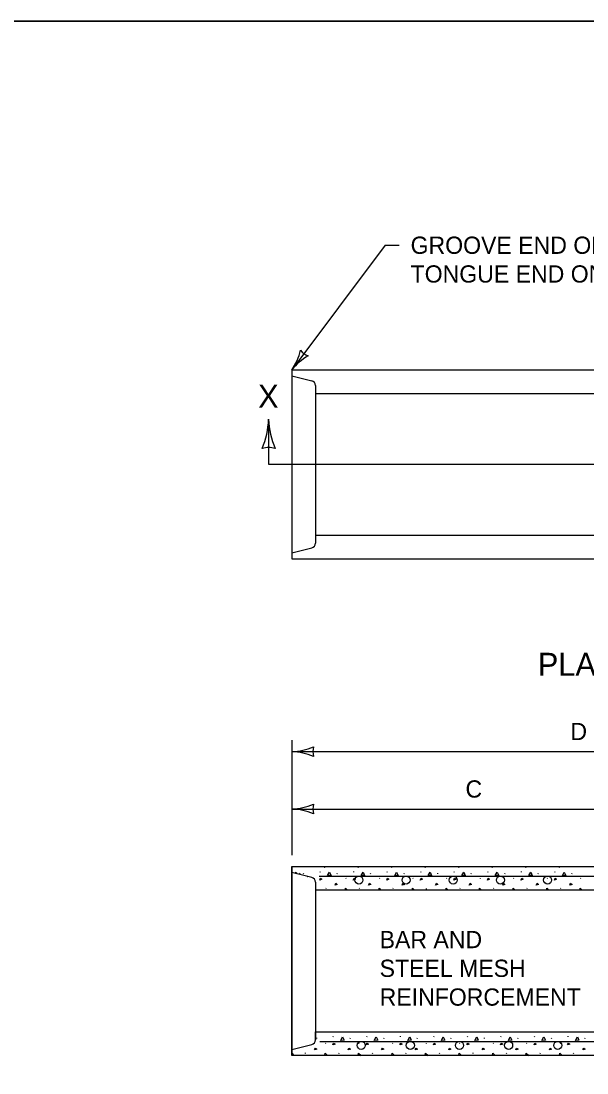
# Model space of a CAD drawing. Extents: x 49991.4 to 50021, y 49987.6 to 50011.4.
# Drawn here: x 50008.666 to 50010.636, y 49995.339 to 49998.999 of the extents above; entities that cross this region are included whole.
import ezdxf

# ---------------------------------------------------------------- set-up
doc = ezdxf.new("R2010")
doc.units = 0
for name, color, linetype in [('Level 1', 7, 'Continuous'), ('Level 2', 7, 'Continuous'), ('Level 3', 7, 'Continuous'), ('Level 4', 7, 'Continuous'), ('Level 6', 7, 'Continuous')]:
    doc.layers.add(name, color=color, linetype=linetype)

msp = doc.modelspace()

# ---------------------------------------------------------------- linework, layer by layer
at = {"layer": 'Level 1'}
for p, q in [((50009.6084, 49997.7858), (50009.6084, 49997.1282)), ((50009.6084, 49997.7858), (50010.8686, 49997.7858)), ((50009.6084, 49997.1282), (50010.8686, 49997.1282)), ((50009.6084, 49996.0573), (50010.8686, 49996.0573)), ((50009.6084, 49996.0573), (50009.6084, 49995.3998)), ((50009.6084, 49995.3998), (50009.6084, 49996.0573)), ((50009.6084, 49995.4204), (50009.6084, 49996.0573)), ((50009.6782, 49996.019), (50009.6084, 49996.0367)), ((50009.6362, 49996.0335), (50009.6372, 49996.0357)), ((50009.6693, 49996.0561), (50009.6698, 49996.0573)), ((50009.7073, 49996.038), (50009.7083, 49996.0402)), ((50009.7217, 49996.0561), (50009.7227, 49996.0546)), ((50009.7227, 49996.0555), (50009.7236, 49996.0541)), ((50009.786, 49996.0561), (50009.7865, 49996.0573)), ((50009.824, 49996.038), (50009.825, 49996.0402)), ((50009.8384, 49996.0561), (50009.8394, 49996.0546)), ((50009.8394, 49996.0555), (50009.8403, 49996.0541)), ((50009.9027, 49996.0561), (50009.9032, 49996.0573)), ((50009.9407, 49996.038), (50009.9417, 49996.0402)), ((50009.9551, 49996.0561), (50009.956, 49996.0546)), ((50009.956, 49996.0555), (50009.957, 49996.0541)), ((50010.0194, 49996.0561), (50010.0199, 49996.0573)), ((50010.0574, 49996.038), (50010.0584, 49996.0402)), ((50010.0718, 49996.0561), (50010.0727, 49996.0546)), ((50010.0727, 49996.0555), (50010.0737, 49996.0541)), ((50010.1361, 49996.0561), (50010.1366, 49996.0573)), ((50010.1741, 49996.038), (50010.175, 49996.0402)), ((50010.1884, 49996.0561), (50010.1894, 49996.0546)), ((50010.1894, 49996.0555), (50010.1904, 49996.0541)), ((50010.2528, 49996.0561), (50010.2533, 49996.0573)), ((50010.2908, 49996.038), (50010.2917, 49996.0402)), ((50010.3051, 49996.0561), (50010.3061, 49996.0546)), ((50010.3061, 49996.0555), (50010.3071, 49996.0541)), ((50010.3694, 49996.0561), (50010.3699, 49996.0573)), ((50010.4075, 49996.038), (50010.4084, 49996.0402)), ((50010.4218, 49996.0561), (50010.4228, 49996.0546)), ((50010.4228, 49996.0555), (50010.4238, 49996.0541)), ((50010.4861, 49996.0561), (50010.4866, 49996.0573)), ((50010.5241, 49996.038), (50010.5251, 49996.0402)), ((50010.5385, 49996.0561), (50010.5395, 49996.0546)), ((50010.5395, 49996.0555), (50010.5405, 49996.0541)), ((50010.6028, 49996.0561), (50010.6033, 49996.0573)), ((50009.6496, 49996.0324), (50009.6506, 49996.0346)), ((50009.6778, 49996.0193), (50009.678, 49996.019)), ((50009.6906, 49996.0031), (50009.6906, 49995.454)), ((50009.7663, 49996.0324), (50009.7672, 49996.0346)), ((50009.7967, 49996.0169), (50009.7977, 49996.0154)), ((50009.883, 49996.0324), (50009.8839, 49996.0346)), ((50009.9134, 49996.0169), (50009.9144, 49996.0154)), ((50009.9996, 49996.0324), (50010.0006, 49996.0346)), ((50010.0301, 49996.0169), (50010.0311, 49996.0154)), ((50010.1163, 49996.0324), (50010.1173, 49996.0346)), ((50010.1468, 49996.0169), (50010.1478, 49996.0154)), ((50010.233, 49996.0324), (50010.234, 49996.0346)), ((50010.2635, 49996.0169), (50010.2645, 49996.0154)), ((50010.3497, 49996.0324), (50010.3507, 49996.0346)), ((50010.3802, 49996.0169), (50010.3811, 49996.0154)), ((50010.4664, 49996.0324), (50010.4674, 49996.0346)), ((50010.4969, 49996.0169), (50010.4978, 49996.0154)), ((50010.5831, 49996.0324), (50010.5841, 49996.0346)), ((50010.6135, 49996.0169), (50010.6145, 49996.0154)), ((50010.8686, 49995.975), (50009.6906, 49995.975)), ((50009.7268, 49995.9806), (50009.7278, 49995.9827)), ((50009.8435, 49995.9806), (50009.8445, 49995.9827)), ((50009.9602, 49995.9806), (50009.9612, 49995.9827)), ((50010.0758, 49995.9788), (50010.0765, 49995.9778)), ((50010.0769, 49995.9806), (50010.0778, 49995.9827)), ((50010.1936, 49995.9806), (50010.1945, 49995.9827)), ((50010.3103, 49995.9806), (50010.3112, 49995.9827)), ((50010.4269, 49995.9806), (50010.4279, 49995.9827)), ((50010.5436, 49995.9806), (50010.5446, 49995.9827)), ((50009.6906, 49995.4819), (50011.6084, 49995.4819)), ((50009.6906, 49995.454), (50009.6906, 49995.4819)), ((50009.6952, 49995.4589), (50009.6962, 49995.4611)), ((50009.7529, 49995.4645), (50009.7539, 49995.4667)), ((50009.7678, 49995.4819), (50009.7683, 49995.4811)), ((50009.7683, 49995.482), (50009.7692, 49995.4806)), ((50009.8119, 49995.4589), (50009.8129, 49995.4611)), ((50009.8696, 49995.4645), (50009.8706, 49995.4667)), ((50009.8845, 49995.4819), (50009.885, 49995.4811)), ((50009.885, 49995.482), (50009.8859, 49995.4806)), ((50009.9286, 49995.4589), (50009.9295, 49995.4611)), ((50009.9863, 49995.4645), (50009.9873, 49995.4667)), ((50010.0012, 49995.4819), (50010.0017, 49995.4811)), ((50010.0017, 49995.482), (50010.0026, 49995.4806)), ((50010.0453, 49995.4589), (50010.0462, 49995.4611)), ((50010.103, 49995.4645), (50010.104, 49995.4667)), ((50010.1178, 49995.4819), (50010.1183, 49995.4811)), ((50010.1183, 49995.482), (50010.1193, 49995.4806)), ((50010.1619, 49995.4589), (50010.1629, 49995.4611)), ((50010.2197, 49995.4645), (50010.2207, 49995.4667)), ((50010.2345, 49995.4819), (50010.235, 49995.4811)), ((50010.235, 49995.482), (50010.236, 49995.4806)), ((50010.2786, 49995.4589), (50010.2796, 49995.4611)), ((50010.3364, 49995.4645), (50010.3373, 49995.4667)), ((50010.3512, 49995.4819), (50010.3517, 49995.4811)), ((50010.3517, 49995.482), (50010.3527, 49995.4806)), ((50010.3953, 49995.4589), (50010.3963, 49995.4611)), ((50010.4531, 49995.4645), (50010.454, 49995.4667)), ((50010.4679, 49995.4819), (50010.4684, 49995.4811)), ((50010.4684, 49995.482), (50010.4694, 49995.4806)), ((50010.512, 49995.4589), (50010.513, 49995.4611)), ((50010.5698, 49995.4645), (50010.5707, 49995.4667)), ((50010.5846, 49995.4819), (50010.5851, 49995.4811)), ((50010.5851, 49995.482), (50010.5861, 49995.4806)), ((50010.6287, 49995.4589), (50010.6297, 49995.4611)), ((50009.6084, 49995.4204), (50009.6782, 49995.4381)), ((50009.7256, 49995.4434), (50009.7266, 49995.4419)), ((50009.8423, 49995.4434), (50009.8433, 49995.4419)), ((50009.959, 49995.4434), (50009.96, 49995.4419)), ((50010.0757, 49995.4434), (50010.0767, 49995.4419)), ((50010.1924, 49995.4434), (50010.1934, 49995.4419)), ((50010.3091, 49995.4434), (50010.3101, 49995.4419)), ((50010.4258, 49995.4434), (50010.4268, 49995.4419)), ((50010.5425, 49995.4434), (50010.5434, 49995.4419)), ((50011.6084, 49995.3998), (50009.6084, 49995.3998)), ((50009.6557, 49995.4071), (50009.6567, 49995.4092)), ((50009.7724, 49995.4071), (50009.7734, 49995.4092)), ((50009.8891, 49995.4071), (50009.8901, 49995.4092)), ((50010.0058, 49995.4071), (50010.0068, 49995.4092)), ((50010.1225, 49995.4071), (50010.1235, 49995.4092)), ((50010.2392, 49995.4071), (50010.2401, 49995.4092)), ((50010.3559, 49995.4071), (50010.3568, 49995.4092)), ((50010.4726, 49995.4071), (50010.4735, 49995.4092)), ((50010.5892, 49995.4071), (50010.5902, 49995.4092))]:
    msp.add_line(p, q, dxfattribs=at)
msp.add_lwpolyline([(49999.3835, 49998.9992), (50016.7501, 49998.9992), (50016.7501, 49987.7988), (49999.3835, 49987.7988)], close=True, dxfattribs=at)
for points in [[(50009.6208, 49996.0336), (50009.6233, 49996.0383), (50009.626, 49996.0322)], [(50009.7334, 49996.0259), (50009.74, 49996.0383), (50009.7451, 49996.0268), (50009.7336, 49996.0259)], [(50009.8501, 49996.0259), (50009.8567, 49996.0383), (50009.8618, 49996.0268), (50009.8503, 49996.0259)], [(50009.9668, 49996.0259), (50009.9733, 49996.0383), (50009.9785, 49996.0268), (50009.967, 49996.0259)], [(50010.0835, 49996.0259), (50010.09, 49996.0383), (50010.0951, 49996.0268), (50010.0837, 49996.0259)], [(50010.2001, 49996.0259), (50010.2067, 49996.0383), (50010.2118, 49996.0268), (50010.2004, 49996.0259)], [(50010.3168, 49996.0259), (50010.3234, 49996.0383), (50010.3285, 49996.0268), (50010.3171, 49996.0259)], [(50010.4335, 49996.0259), (50010.4401, 49996.0383), (50010.4452, 49996.0268), (50010.4338, 49996.0259)], [(50010.5502, 49996.0259), (50010.5568, 49996.0383), (50010.5619, 49996.0268), (50010.5505, 49996.0259)], [(50009.6623, 49996.0213), (50009.6625, 49996.0216)], [(50009.6629, 49996.0213), (50009.6625, 49996.0213)], [(50009.7037, 49996.0243), (50010.8526, 49996.0243)], [(50009.7056, 49996.0105), (50009.7085, 49996.0166), (50009.7134, 49996.013), (50009.7056, 49996.0105)], [(50009.759, 49995.9931), (50009.7619, 49995.9992), (50009.7668, 49995.9955), (50009.759, 49995.9931)], [(50009.8223, 49996.0105), (50009.8252, 49996.0166), (50009.8301, 49996.013), (50009.8223, 49996.0105)], [(50009.8757, 49995.9931), (50009.8786, 49995.9992), (50009.8835, 49995.9955), (50009.8757, 49995.9931)], [(50009.939, 49996.0105), (50009.9419, 49996.0166), (50009.9468, 49996.013), (50009.939, 49996.0105)], [(50009.9924, 49995.9931), (50009.9953, 49995.9992), (50010.0002, 49995.9955), (50009.9924, 49995.9931)], [(50010.0557, 49996.0105), (50010.0586, 49996.0166), (50010.0635, 49996.013), (50010.0557, 49996.0105)], [(50010.1091, 49995.9931), (50010.112, 49995.9992), (50010.1169, 49995.9955), (50010.1091, 49995.9931)], [(50010.1724, 49996.0105), (50010.1753, 49996.0166), (50010.1802, 49996.013), (50010.1724, 49996.0105)], [(50010.2258, 49995.9931), (50010.2287, 49995.9992), (50010.2336, 49995.9955), (50010.2258, 49995.9931)], [(50010.2891, 49996.0105), (50010.292, 49996.0166), (50010.2969, 49996.013), (50010.2891, 49996.0105)], [(50010.3425, 49995.9931), (50010.3454, 49995.9992), (50010.3503, 49995.9955), (50010.3425, 49995.9931)], [(50010.4057, 49996.0105), (50010.4087, 49996.0166), (50010.4135, 49996.013), (50010.4057, 49996.0105)], [(50010.4591, 49995.9931), (50010.4621, 49995.9992), (50010.4669, 49995.9955), (50010.4591, 49995.9931)], [(50010.5224, 49996.0105), (50010.5254, 49996.0166), (50010.5302, 49996.013), (50010.5224, 49996.0105)], [(50010.5758, 49995.9931), (50010.5788, 49995.9992), (50010.5836, 49995.9955), (50010.5758, 49995.9931)], [(50009.7945, 49995.975), (50009.7954, 49995.982), (50009.8022, 49995.975)], [(50009.9112, 49995.975), (50009.9121, 49995.982), (50009.9189, 49995.975)], [(50010.0278, 49995.975), (50010.0288, 49995.982), (50010.0356, 49995.975)], [(50010.1445, 49995.975), (50010.1455, 49995.982), (50010.1523, 49995.975)], [(50010.2612, 49995.975), (50010.2622, 49995.982), (50010.269, 49995.975)], [(50010.3779, 49995.975), (50010.3788, 49995.982), (50010.3856, 49995.975)], [(50010.4946, 49995.975), (50010.4955, 49995.982), (50010.5023, 49995.975)], [(50010.6113, 49995.975), (50010.6122, 49995.982), (50010.619, 49995.975)], [(50009.779, 49995.4524), (50009.7856, 49995.4648), (50009.7907, 49995.4533), (50009.7792, 49995.4524)], [(50009.8957, 49995.4524), (50009.9023, 49995.4648), (50009.9074, 49995.4533), (50009.8959, 49995.4524)], [(50010.0124, 49995.4524), (50010.019, 49995.4648), (50010.0241, 49995.4533), (50010.0126, 49995.4524)], [(50010.1291, 49995.4524), (50010.1356, 49995.4648), (50010.1408, 49995.4533), (50010.1293, 49995.4524)], [(50010.2458, 49995.4524), (50010.2523, 49995.4648), (50010.2574, 49995.4533), (50010.246, 49995.4524)], [(50010.3624, 49995.4524), (50010.369, 49995.4648), (50010.3741, 49995.4533), (50010.3627, 49995.4524)], [(50010.4791, 49995.4524), (50010.4857, 49995.4648), (50010.4908, 49995.4533), (50010.4794, 49995.4524)], [(50010.5958, 49995.4524), (50010.6024, 49995.4648), (50010.6075, 49995.4533), (50010.5961, 49995.4524)], [(50009.6879, 49995.4196), (50009.6909, 49995.4257), (50009.6957, 49995.422), (50009.6879, 49995.4196)], [(50009.706, 49995.4491), (50011.5866, 49995.4491)], [(50009.7512, 49995.437), (50009.7541, 49995.4431), (50009.759, 49995.4395), (50009.7512, 49995.437)], [(50009.8046, 49995.4196), (50009.8075, 49995.4257), (50009.8124, 49995.422), (50009.8046, 49995.4196)], [(50009.8679, 49995.437), (50009.8708, 49995.4431), (50009.8757, 49995.4395), (50009.8679, 49995.437)], [(50009.9213, 49995.4196), (50009.9242, 49995.4257), (50009.9291, 49995.422), (50009.9213, 49995.4196)], [(50009.9846, 49995.437), (50009.9875, 49995.4431), (50009.9924, 49995.4395), (50009.9846, 49995.437)], [(50010.038, 49995.4196), (50010.0409, 49995.4257), (50010.0458, 49995.422), (50010.038, 49995.4196)], [(50010.1013, 49995.437), (50010.1042, 49995.4431), (50010.1091, 49995.4395), (50010.1013, 49995.437)], [(50010.1547, 49995.4196), (50010.1576, 49995.4257), (50010.1625, 49995.422), (50010.1547, 49995.4196)], [(50010.218, 49995.437), (50010.2209, 49995.4431), (50010.2258, 49995.4395), (50010.218, 49995.437)], [(50010.2714, 49995.4196), (50010.2743, 49995.4257), (50010.2792, 49995.422), (50010.2714, 49995.4196)], [(50010.3347, 49995.437), (50010.3376, 49995.4431), (50010.3425, 49995.4395), (50010.3347, 49995.437)], [(50010.3881, 49995.4196), (50010.391, 49995.4257), (50010.3959, 49995.422), (50010.3881, 49995.4196)], [(50010.4514, 49995.437), (50010.4543, 49995.4431), (50010.4592, 49995.4395), (50010.4514, 49995.437)], [(50010.5048, 49995.4196), (50010.5077, 49995.4257), (50010.5126, 49995.422), (50010.5048, 49995.4196)], [(50010.568, 49995.437), (50010.571, 49995.4431), (50010.5758, 49995.4395), (50010.568, 49995.437)], [(50010.6214, 49995.4196), (50010.6244, 49995.4257), (50010.6292, 49995.422), (50010.6214, 49995.4196)], [(50009.6084, 49995.4077), (50009.6161, 49995.3998)], [(50009.7231, 49995.3998), (50009.7243, 49995.4085), (50009.7327, 49995.3998)], [(50009.8398, 49995.3998), (50009.841, 49995.4085), (50009.8494, 49995.3998)], [(50009.9565, 49995.3998), (50009.9577, 49995.4085), (50009.9661, 49995.3998)], [(50010.0732, 49995.3998), (50010.0744, 49995.4085), (50010.0828, 49995.3998)], [(50010.1899, 49995.3998), (50010.1911, 49995.4085), (50010.1995, 49995.3998)], [(50010.3066, 49995.3998), (50010.3078, 49995.4085), (50010.3162, 49995.3998)], [(50010.4233, 49995.3998), (50010.4245, 49995.4085), (50010.4329, 49995.3998)], [(50010.5399, 49995.3998), (50010.5411, 49995.4085), (50010.5496, 49995.3998)]]:
    msp.add_lwpolyline(points, dxfattribs=at)
for centre in [(50009.8421, 49996.0104), (50010.0062, 49996.0104), (50010.1703, 49996.0104), (50010.3344, 49996.0104), (50010.4986, 49996.0104), (50009.8502, 49995.4351), (50010.0211, 49995.4351), (50010.1921, 49995.4351), (50010.3631, 49995.4351), (50010.534, 49995.4351)]:
    msp.add_circle(centre, 0.014, dxfattribs=at)
for centre, start, end in [((50009.6742, 49996.003), 0, 75.8703), ((50009.6742, 49995.454), 284.1107, 0)]:
    msp.add_arc(centre, 0.0164, start, end, dxfattribs=at)
at = {"layer": 'Level 2'}
msp.add_line((50016.7501, 49998.9992), (49999.3835, 49998.9992), dxfattribs=at)
at = {"layer": 'Level 3'}
for p, q in [((50009.9333, 49998.2192), (50009.6084, 49997.7858)), ((50009.9333, 49998.2192), (50009.982, 49998.2192)), ((50009.6084, 49996.4973), (50009.6084, 49996.0973)), ((50009.6084, 49996.4573), (50011.6084, 49996.4573)), ((50009.6084, 49996.2573), (50010.8686, 49996.2573))]:
    msp.add_line(p, q, dxfattribs=at)
for centre, radius, start, end in [((50009.4231, 49997.911), 0.2237, 325.9574, 345.2073), ((50009.7737, 49997.6508), 0.2134, 120.5861, 140.7696), ((50009.6823, 49997.8843), 0.0526, 215.2689, 250.9913), ((50009.2318, 49997.6258), 0.2964, 337.456, 357.6395), ((50009.8383, 49997.6289), 0.3107, 182.8273, 202.0772), ((50009.528, 49997.4426), 0.073, 72.1388, 107.8612), ((50009.5969, 49996.69), 0.233, 272.8273, 292.0772), ((50009.7366, 49996.4573), 0.0548, 162.1388, 197.8612), ((50009.5992, 49996.2352), 0.2223, 67.456, 87.6395), ((50009.5969, 49996.49), 0.233, 272.8273, 292.0772), ((50009.5992, 49996.0352), 0.2223, 67.456, 87.6395), ((50009.7366, 49996.2573), 0.0548, 162.1388, 197.8612)]:
    msp.add_arc(centre, radius, start, end, dxfattribs=at)
at = {"layer": 'Level 4'}
for p, q in [((50009.6084, 49997.7651), (50009.6782, 49997.7474)), ((50009.6906, 49997.7316), (50009.6906, 49997.1825)), ((50009.6906, 49997.7037), (50010.8686, 49997.7037)), ((50009.6906, 49997.2105), (50010.8686, 49997.2105)), ((50009.6084, 49997.149), (50009.6782, 49997.1666))]:
    msp.add_line(p, q, dxfattribs=at)
for centre, start, end in [((50009.6742, 49997.7316), 0, 75.8576), ((50009.6742, 49997.1826), 284.1764, 0)]:
    msp.add_arc(centre, 0.0164, start, end, dxfattribs=at)
at = {"layer": 'Level 6'}
for p, q in [((50009.528, 49997.6136), (50009.528, 49997.457)), ((50009.528, 49997.457), (50011.6931, 49997.457))]:
    msp.add_line(p, q, dxfattribs=at)

# ---------------------------------------------------------------- texts
at = {"layer": 'Level 2'}
for s, height, p in [('GROOVE END ON OUTLET END SECTIONS', 0.06, (50010.022, 49998.1892)), ('TONGUE END ON INLET END SECTIONS', 0.06, (50010.022, 49998.0892)), ('X', 0.08, (50009.4913, 49997.6536)), ('PLAN', 0.08, (50010.4646, 49996.721)), ('D', 0.06, (50010.5781, 49996.4973)), ('C', 0.06, (50010.213, 49996.2973)), ('BAR AND', 0.06, (50009.9142, 49995.7734)), ('STEEL MESH', 0.06, (50009.9142, 49995.6734)), ('REINFORCEMENT', 0.06, (50009.9142, 49995.5734))]:
    msp.add_text(s, height=height, dxfattribs=at).set_placement(p)

doc.saveas('drawing.dxf')
